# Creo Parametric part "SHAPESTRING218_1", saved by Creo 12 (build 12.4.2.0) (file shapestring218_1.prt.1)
Units: Custom; MM, KILOGRAM, SECS

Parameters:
  PTC_WM_ITERATION = "0"
  PTC_WM_VERSION = "-.0"
  PTC_WM_LIFECYCLE_STATE = "In Work"
  PTC_WM_LIFECYCLE = "MO_CADDocument"
  PTC_WM_CREATED_BY = "Maximilian Roepper (Z0017RMS: MO)"
  PTC_WM_CREATED_ON = "18-Sep-26 11:36:42 AM"
  PTC_WM_MODIFIED_BY = "Maximilian Roepper (Z0017RMS: MO)"
  PTC_WM_MODIFIED_ON = "18-Sep-26 11:36:46 AM"
  PDMLINKNUMBER = "PDM000071454958"
  PTC_WM_NAME = "shapestring218_1.prt"
  PTC_WM_NUMBER = "PDM000071454958"

Other parameters: WEIGHT, WEIGHT_FACTOR, WEIGHT_ADD, _MASS_TEMP, _DIFF_TEMP, MC_ERRORS, SUPPLIER

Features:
  1. coordinate system
  2. datum plane "PRT_YZ"
  3. datum plane "PRT_XY"
  4. datum plane "PRT_XZ"
  5. coordinate system
  6. datum axis
  7. datum axis
  8. datum axis
  9. coordinate system
  10. imported feature

Other named items: PRT, SIEMENS_MO, DRW_VIEW_ORG, PRT_X, PRT_Y, PRT_Z, CS0, ROUGH_GROB

Layers: 00_STD_CSYS-KSYS, 01_STD_PLANES-EBENEN, 02_STD_AXES-ACHSEN, 03_STD_CSYS-KSYS, 24_IMPORT_FEAT-IMPORT_KE, INTFCLR

Surfaces: 1 plane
